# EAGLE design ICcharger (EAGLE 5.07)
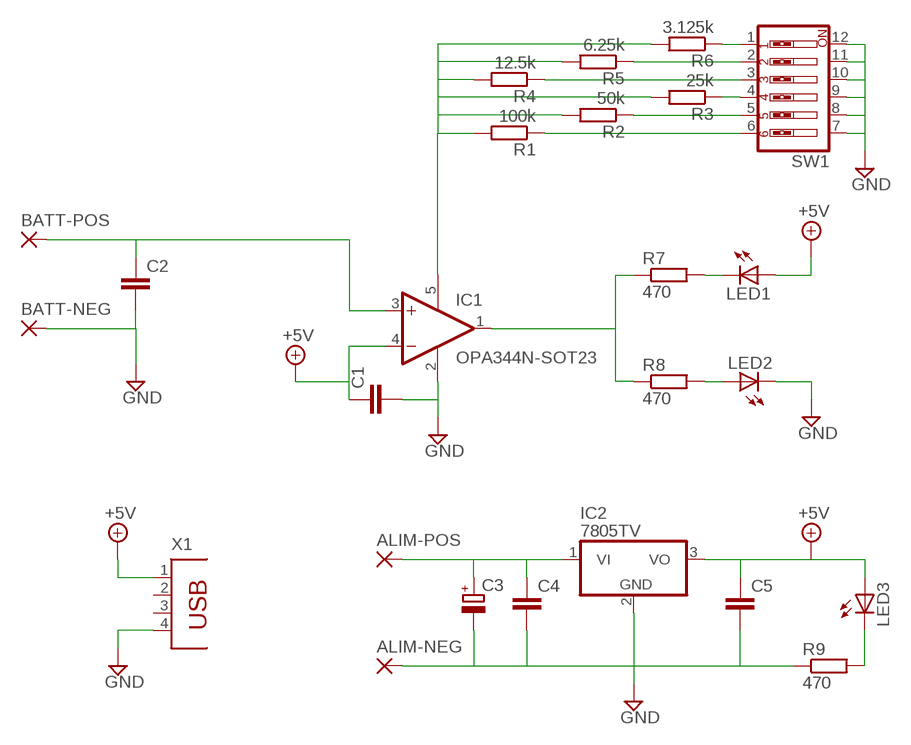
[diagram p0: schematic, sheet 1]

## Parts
ALIM-NEG  3,81/1,4  [3,81/1,4]
ALIM-POS  3,81/1,4  [3,81/1,4]
BATT-NEG  3,81/1,4  [3,81/1,4]
BATT-POS  3,81/1,4  [3,81/1,4]
C1  C-EU025-025X050  [C025-025X050]
C2  C-EU025-025X050  [C025-025X050]
C3  CPOL-EUE5-6  [E5-6]
C4  C-EU050-030X075  [C050-030X075]
C5  C-EU050-030X075  [C050-030X075]
IC1  OPA344N-SOT23  [SOT23-5]
IC2  7805TV  [TO220V]
LED1  LED3MM  [LED3MM]
LED2  LED3MM  [LED3MM]
LED3  LED3MM  [LED3MM]
R1  100k  R-EU_0204/5  [0204/5]
R2  50k  R-EU_0204/5  [0204/5]
R3  25k  R-EU_0204/5  [0204/5]
R4  12.5k  R-EU_0204/5  [0204/5]
R5  6.25k  R-EU_0204/5  [0204/5]
R6  3.125k  R-EU_0204/5  [0204/5]
R7  470  R-EU_0204/7  [0204/7]
R8  470  R-EU_0204/5  [0204/5]
R9  470  R-EU_0204/5  [0204/5]
SW1  SW_DIP-6  [EDG-06]
X1  PN87520  [PN87520]

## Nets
+5V: C1.1 C5.1 IC1.4(-IN) IC2.3(VO) LED1.A LED3.A X1.1
GND: ALIM-NEG.1(P) BATT-NEG.1(P) C1.2 C2.2 C3.- C4.2 C5.2 IC1.2(V-) IC2.2(GND) LED2.K(C) R9.1 SW1.7 SW1.8 SW1.9 SW1.10 SW1.11 SW1.12 X1.4
N$1: BATT-POS.1(P) C2.1 IC1.3(+IN)
N$2: R1.1 SW1.6
N$3: R2.1 SW1.5
N$4: R3.1 SW1.4
N$5: R4.1 SW1.3
N$6: R5.1 SW1.2
N$7: R6.1 SW1.1
N$8: IC1.5(V+) R1.2 R2.2 R3.2 R4.2 R5.2 R6.2
N$9: LED1.K(C) R7.2
N$10: ALIM-POS.1(P) C3.+ C4.1 IC2.1(VI)
N$11: LED2.A R8.2
N$12: IC1.1(OUT) R7.1 R8.1
N$14: LED3.K(C) R9.2
Unconnected: X1.2 X1.3

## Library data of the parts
ALIM-NEG ALIM-POS BATT-NEG BATT-POS = wirepad:3,81/1,4: THROUGH-HOLE PAD
C1 C2 C4 C5 = rcl:C-EU: CAPACITOR, European symbol
C3 = rcl:CPOL-EU: POLARIZED CAPACITOR, European symbol
IC1 = linear:OPA*-SOT23: Single Operational Amplifier Low Power, Single-Supply, Rail-To-Rail Operational Amplifier Source: http://focus.ti.com/lit/ds/symlink/opa2345.pdf
IC2 = linear:78*: Positive VOLTAGE REGULATOR Source: http://cache.national.com/ds/LM/LM78L05.pdf http://www.fairchildsemi.com/ds/LM/LM7805.pdf
LED1-LED3 = led:LED: LED
R1-R9 = resistor:R-EU_: RESISTOR, European symbol
SW1 = special:SW_DIP-6: DIP SWITCH
X1 = con-berg:PN87520: BERG USB connector

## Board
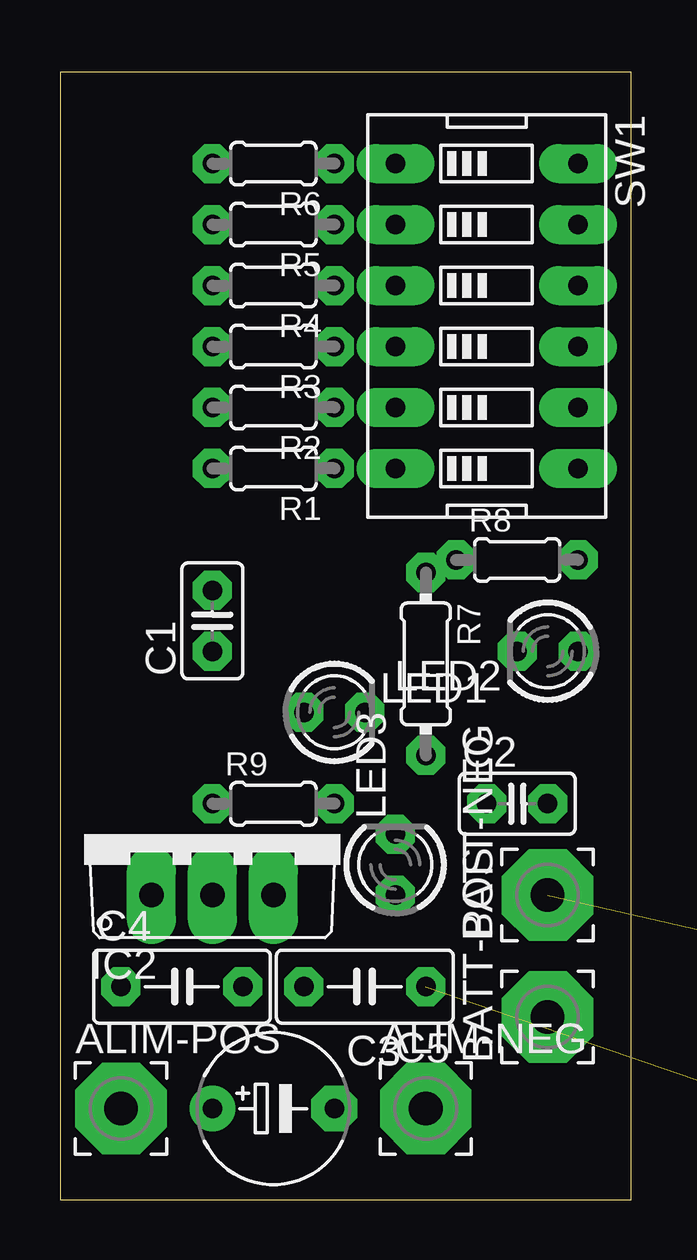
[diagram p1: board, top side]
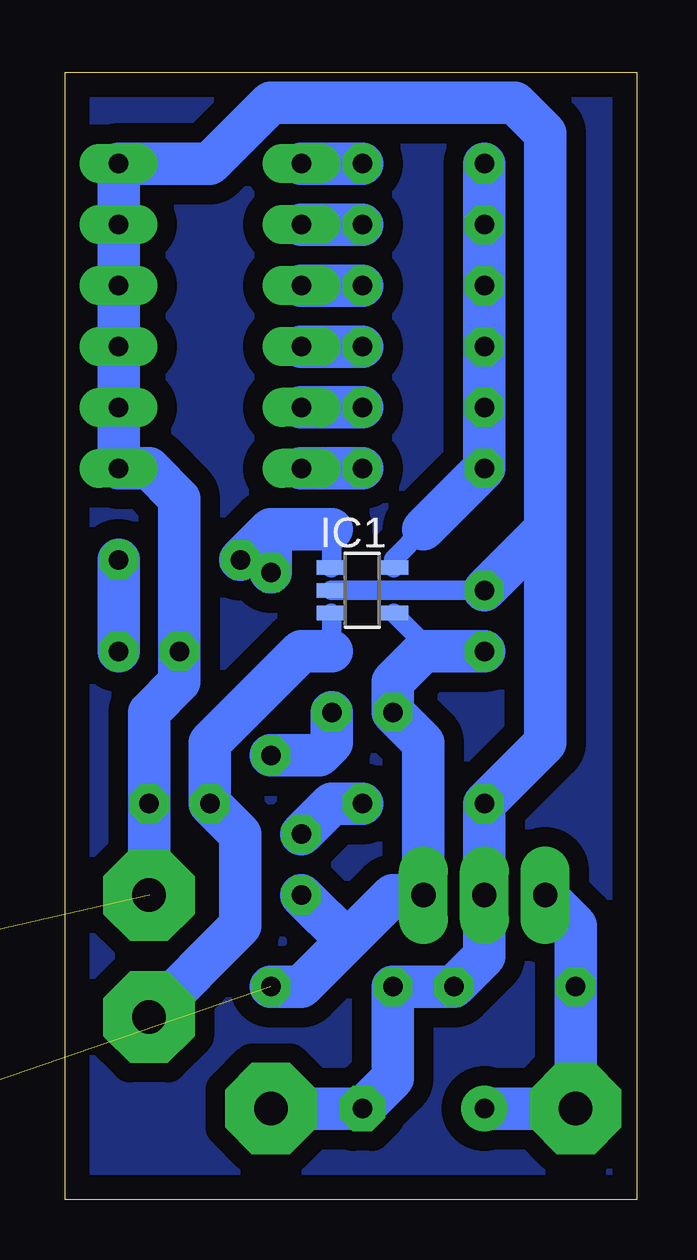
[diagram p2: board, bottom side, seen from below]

Size 23.8 x 46.98 mm. Coordinates in mm from the lower left corner, seen from the top.
Outline: 0,0 23.8,0 23.8,46.98 0,46.98 0,0
Copper layers (1*16): Top 0.035mm / dielectric 1.5mm / Bottom 0.035mm
Design rules "default *": minimum track width 10mil, minimum drill 24mil, track to track 8mil, track to pad 8mil, pad to pad 8mil, via to via 8mil, smd to smd 8mil, copper to edge 40mil, drill to drill 8mil, minimum pad ring 10mil, minimum via ring 8mil, stop-mask expansion 4mil, vias tented up to drill 0mil, thermal gap 10mil

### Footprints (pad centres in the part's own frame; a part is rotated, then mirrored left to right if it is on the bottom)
3,81/1,4 = drill 1.397 pad 3.81 octagon: 1 0,0
C025-025X050 = drill 0.813 octagon: 1 -1.27,0; 2 1.27,0
E5-6 = drill 0.813 pad 1.905 round: + -2.54,0 | drill 0.813 pad 1.905 octagon: - 2.54,0
C050-030X075 = drill 0.813 octagon: 1 -2.54,0; 2 2.54,0
SOT23-5 = smd 0.6 x 1.2: 1 -0.95,-1.306; 2 0,-1.306; 3 0.95,-1.306; 4 0.95,1.306; 5 -0.95,1.306
TO220V = drill 1.016 long: 1 -2.54,-2.54; 2 0,-2.54; 3 2.54,-2.54
LED3MM = drill 0.813 octagon: A -1.27,0; K 1.27,0
0204/5 = drill 0.813 octagon: 1 -2.54,0; 2 2.54,0
0204/7 = drill 0.813 octagon: 1 -3.81,0; 2 3.81,0
EDG-06 = drill 0.813 long: 1 -6.35,-3.81; 2 -3.81,-3.81; 3 -1.27,-3.81; 4 1.27,-3.81; 5 3.81,-3.81; 6 6.35,-3.81; 7 6.35,3.81; 8 3.81,3.81; 9 1.27,3.81; 10 -1.27,3.81; 11 -3.81,3.81; 12 -6.35,3.81
PN87520 = drill 0.95 long: 1 -3.5,2.71; 2 -1,2.71; 3 1,2.71; 4 3.5,2.71 | hole 2.3: -6.57,0; 6.57,0

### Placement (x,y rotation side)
ALIM-NEG  15.24,3.81 0 top
ALIM-POS  2.54,3.81 0 top
BATT-NEG  20.32,12.7 90 top
BATT-POS  20.32,7.62 90 top
C1  6.35,24.13 90 top
C2  19.05,16.51 0 top
C3  8.89,3.81 0 top
C4  5.08,8.89 0 top
C5  12.7,8.89 180 top
IC1  11.43,25.4 270 bottom
IC2  6.35,15.24 0 top
LED1  11.43,20.32 0 top
LED2  20.32,22.86 180 top
LED3  13.97,13.97 90 top
R1  8.89,30.48 180 top
R2  8.89,33.02 180 top
R3  8.89,35.56 180 top
R4  8.89,38.1 180 top
R5  8.89,40.64 180 top
R6  8.89,43.18 180 top
R7  15.24,22.33 270 top
R8  19.05,26.67 0 top
R9  8.89,16.51 0 top
SW1  17.78,36.83 270 top
X1  not placed on the board

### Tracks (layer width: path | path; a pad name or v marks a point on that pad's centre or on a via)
+5V  (1 unrouted)
  Bottom 0.813: 8.89,22.86 8.89,23.22 IC1.4
  Bottom 1.778: C1.1 8.89,22.86 10.16,21.59 LED1.A 8.89,19.05 IC2.3 10.16,12.7 12.06,10.79 | 12.06,10.79 13.97,8.89 C5.1 | 12.06,10.79 LED3.A
GND  (1 unrouted)
  Bottom 0.813: C1.2 IC1.2
  Bottom 1.778: 3.81,27.94 3.81,44.45 5.08,45.72 15.24,45.72 17.78,43.18 SW1.12 SW1.11 SW1.10 SW1.9 SW1.8 SW1.7 20.32,30.48 19.05,29.21 LED2.K 19.05,21.59 20.32,20.32 C2.2 BATT-NEG.1 | 3.81,27.94 C1.2 | ALIM-NEG.1 C3.- 10.16,5.08 C5.2 C4.2 6.35,10.16 IC2.2 R9.1 3.81,19.05 3.81,27.94
N$1
  Bottom 0.813: 12.7,22.86 12.7,24.41 IC1.3
  Bottom 1.778: BATT-POS.1 16.51,11.43 16.51,15.24 C2.1 17.78,19.05 13.97,22.86 12.7,22.86
N$2
  Bottom 1.778: R1.1 SW1.6
N$3
  Bottom 1.778: R2.1 SW1.5
N$4
  Bottom 1.778: R3.1 SW1.4
N$5
  Bottom 1.778: R4.1 SW1.3
N$6
  Bottom 1.778: R5.1 SW1.2
N$7
  Bottom 1.778: R6.1 SW1.1
N$8
  Bottom 0.813: IC1.5 10.12,26.71 8.89,27.94
  Bottom 1.778: R6.2 R5.2 R4.2 R3.2 R2.2 R1.2 8.89,27.94
N$9
  Bottom 1.778: LED1.K 12.7,19.05 13.23,18.52 R7.2
N$10
  Bottom 1.778: C3.+ ALIM-POS.1 C4.1 2.54,11.43 IC2.1
N$11
  Bottom 1.778: LED2.A R8.2
N$12
  Bottom 0.813: 12.7,27.94 12.7,26.39 IC1.1
  Bottom 1.778: 12.7,27.94 15.24,27.94 | 15.24,27.94 R7.1 | 15.24,27.94 R8.1
N$13
  pour Bottom (isolate 0.813, no thermals): 0,46.99 24.13,46.99 24.13,0 0,0
N$14
  Bottom 1.778: R9.2 12.7,16.51 LED3.K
